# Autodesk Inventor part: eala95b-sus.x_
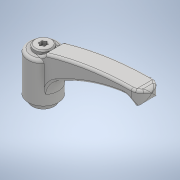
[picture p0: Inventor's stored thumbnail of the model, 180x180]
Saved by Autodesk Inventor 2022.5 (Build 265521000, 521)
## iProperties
Created: 2018-05
Part Number: eala95b-sus.x_
Material: 一般
Document SubType Name: Modeling
Designer: imaocorp
Density: 1 g/cm^3
Appearance: 既定
Sending System: SOLIDWORKS 2016-2016286
MC: AMD64
MC_MODEL: AMD64 Family 21 Model 2 Stepping 0, AuthenticAMD
OS: Windows_NT
FRU: Parasolid Version 28.0, build 224,  7-29-2016
FORMAT: text
GUISE: transmit
KEY: eala95b-sus
FILE: eala95b-sus.x_t
DATE: Fri May 18 11:33:33 2018
Author: imaocorp
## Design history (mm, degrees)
feature "Base1"
node "ソリッド1"
